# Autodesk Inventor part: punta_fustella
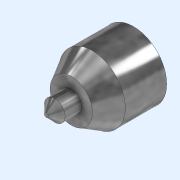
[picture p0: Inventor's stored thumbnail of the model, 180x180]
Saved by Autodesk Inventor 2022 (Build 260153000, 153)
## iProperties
Created: 2022-01
Part Number: punta_fustella
Material: Generico
Document SubType Name: Modeling
Designer: admin
Density: 1 g/cm^3
Appearance: Acciaio galvanizzato
Author: admin
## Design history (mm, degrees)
sketch "Schizzo1"
  geometry: C1 r 5 at (3.845, 0) reference; C2 r 8 at (3.845, 0); 2 further points
  constraints: 1 centre point, 1 coincident, 1 horizontal alignment
  dimensions: "d0" = 16 diameter of C2
extrude "Estrusione1" new body sketch "Schizzo1" distance "d1" = 10; taper "d2" = 0 deg
sketch "Schizzo2"
  geometry: C1 r 8 at (0, 0) reference; 1 further point
extrude "Estrusione2" join sketch "Schizzo2" distance "d3" = 5; taper "d4" = -30 deg
sketch "Schizzo3"
  geometry: C1 r 8 at (0, 0) reference; C2 r 2.5 at (0, 0); 1 further point
  constraints: 1 centre point, 1 coincident
  dimensions: "d5" = 5 diameter of C2
extrude "Estrusione3" join sketch "Schizzo3" distance "d6" = 6; taper "d7" = 0 deg
chamfer "Smusso1" distance "d8" = 2; stored, may be unused: second distance "d9" = 2, angle "d10" = 45 deg
feature "Filettatura1" dims "d11" = 15, "d12" = 0
node "Solido1"
node "Riferimento1"
node "Riferimento2"
